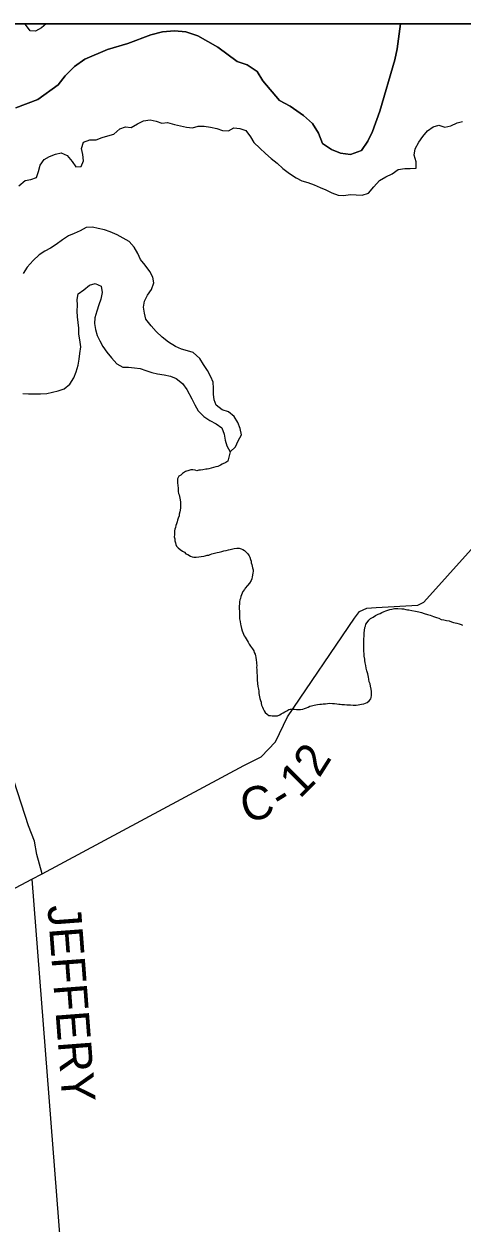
# Model space of a CAD drawing. Extents: x 0.4 to 34.4, y -2.1 to 19.9.
# Drawn here: x 6.349 to 7.097, y 16.79 to 18.836 of the extents above; entities that cross this region are included whole.
import ezdxf

# ---------------------------------------------------------------- set-up
doc = ezdxf.new("R2010")
doc.units = 0
for name, color, linetype in [('GM_X_County', 7, 'Continuous'), ('GM_X_County_Road', 7, 'Continuous'), ('GM_X_County_Road_Text', 7, 'Continuous'), ('GM_X_Major_Lake', 7, 'Continuous'), ('GM_X_Minor_River', 7, 'Continuous'), ('GM_X_Township', 7, 'Continuous'), ('SH_Data', 7, 'Continuous')]:
    doc.layers.add(name, color=color, linetype=linetype)

msp = doc.modelspace()

# ---------------------------------------------------------------- linework, layer by layer
at = {"layer": 'GM_X_County'}
msp.add_lwpolyline([(9.8001, 15.3423), (9.8001, 18.8357), (3.0001, 18.8357), (3.0001, 12.0357), (9.5074, 12.0357)], dxfattribs=at)
at = {"layer": 'GM_X_County_Road'}
for points in [[(5.0993, 16.7069), (5.2822, 16.8039), (5.7558, 17.055), (6.3625, 17.3767), (6.38, 17.386), (6.7247, 17.5708), (6.7542, 17.5855), (6.7786, 17.6112), (6.7991, 17.6537), (6.9135, 17.8219), (6.9221, 17.8335), (6.9343, 17.8393), (6.9503, 17.8402), (7.0217, 17.8445), (7.032, 17.8492), (7.2391, 18.0795)], [(6.38, 17.386), (6.3711, 17.4191), (6.3668, 17.4419), (6.3569, 17.4679), (6.3072, 17.6191), (6.2919, 17.6694), (6.2797, 17.6961), (6.2758, 17.722), (6.2794, 17.7477), (6.2904, 17.8277), (6.2982, 17.9054), (6.2953, 17.9525), (6.2908, 17.9658), (6.2906, 17.9665)], [(6.3625, 17.3767), (6.4528, 16.2176), (6.4539, 16.203)]]:
    msp.add_lwpolyline(points, dxfattribs=at)
at = {"layer": 'GM_X_Major_Lake'}
for points in [[(6.3867, 18.8357), (6.3789, 18.8292), (6.3689, 18.8233), (6.3595, 18.8242), (6.3516, 18.8346), (6.3515, 18.8357)], [(6.3402, 18.5598), (6.3509, 18.5684), (6.3608, 18.5701), (6.3704, 18.5738), (6.3739, 18.5843), (6.3768, 18.5949), (6.3834, 18.6047), (6.3929, 18.6094), (6.4029, 18.6135), (6.4128, 18.616), (6.4229, 18.6113), (6.4311, 18.6013), (6.4374, 18.5917), (6.4469, 18.5923), (6.4505, 18.6025), (6.4495, 18.6131), (6.4474, 18.6234), (6.4506, 18.634), (6.4617, 18.6383), (6.4723, 18.6382), (6.4826, 18.6422), (6.4922, 18.6451), (6.5025, 18.6476), (6.5125, 18.6569)], [(6.5125, 18.6569), (6.5224, 18.6601), (6.5322, 18.6592), (6.543, 18.6651), (6.5533, 18.6703), (6.5643, 18.672), (6.5745, 18.6699), (6.5847, 18.6664), (6.5942, 18.6674), (6.6063, 18.6641), (6.6162, 18.6617), (6.6264, 18.6597), (6.6366, 18.6587), (6.6465, 18.6612), (6.6568, 18.6611), (6.6674, 18.6598), (6.6783, 18.6573), (6.6882, 18.6542), (6.698, 18.6532), (6.7076, 18.6584), (6.7178, 18.6575), (6.728, 18.6539), (6.7358, 18.6432), (6.7414, 18.6336), (6.7515, 18.6236), (6.7616, 18.6147), (6.7713, 18.6062), (6.7811, 18.5981), (6.7908, 18.5892), (6.8024, 18.5807), (6.8137, 18.5733), (6.8235, 18.5682), (6.8337, 18.565), (6.8446, 18.5615), (6.8548, 18.5568), (6.8646, 18.5528), (6.8744, 18.5477), (6.8857, 18.5438), (6.8952, 18.5429), (6.9059, 18.5446), (6.9165, 18.5444), (6.9267, 18.5439), (6.9374, 18.5471), (6.9463, 18.558), (6.956, 18.5688), (6.9671, 18.5751), (6.9778, 18.5799), (6.9881, 18.5877), (6.9992, 18.589), (7.0086, 18.5889), (7.0185, 18.5895), (7.0187, 18.6005), (7.0155, 18.6119), (7.0171, 18.6229), (7.023, 18.6338), (7.03, 18.6439), (7.0381, 18.6536), (7.0477, 18.6603), (7.0576, 18.6628), (7.0678, 18.6596), (7.0777, 18.6621), (7.0884, 18.6669), (7.098, 18.6694)], [(6.7142, 18.1559), (6.7079, 18.1662), (6.6982, 18.1739), (6.6872, 18.1775), (6.6771, 18.1853), (6.6738, 18.1948), (6.6724, 18.2043), (6.6726, 18.2142), (6.672, 18.2244), (6.6683, 18.2339), (6.6624, 18.2446), (6.6558, 18.255), (6.6491, 18.2653), (6.6382, 18.275), (6.628, 18.2782), (6.6182, 18.281), (6.6077, 18.2857), (6.5956, 18.2931), (6.5851, 18.3016), (6.575, 18.3112), (6.5665, 18.3208), (6.5571, 18.332), (6.555, 18.3423), (6.5533, 18.3525), (6.555, 18.3627), (6.5597, 18.3729), (6.5667, 18.383), (6.5706, 18.3943), (6.5693, 18.4038), (6.5641, 18.4134), (6.5559, 18.4241), (6.5481, 18.4341), (6.5437, 18.4441), (6.537, 18.4548), (6.5285, 18.4644), (6.5187, 18.4702), (6.5081, 18.4757), (6.4964, 18.4812), (6.4863, 18.4844), (6.476, 18.4868), (6.4658, 18.4889), (6.4552, 18.4883), (6.4452, 18.4827), (6.4345, 18.4784), (6.425, 18.474), (6.4146, 18.4673), (6.4039, 18.4595), (6.3943, 18.4532), (6.3847, 18.448), (6.3748, 18.4421), (6.3647, 18.4324), (6.3543, 18.4208), (6.3477, 18.4103)], [(6.3472, 18.2056), (6.3566, 18.2047), (6.3669, 18.2049), (6.3775, 18.2047), (6.3882, 18.2053), (6.3977, 18.2078), (6.4076, 18.2099), (6.4175, 18.2132), (6.4275, 18.2214), (6.4341, 18.2319), (6.4381, 18.2424), (6.4417, 18.2534), (6.4433, 18.264), (6.4446, 18.2738), (6.4459, 18.2848), (6.4446, 18.2966), (6.4429, 18.3068), (6.4426, 18.3167), (6.4417, 18.3262), (6.4403, 18.3361), (6.4401, 18.3456), (6.4406, 18.3562), (6.44, 18.3657), (6.4417, 18.3755), (6.4513, 18.3822), (6.4609, 18.3904), (6.4708, 18.3932), (6.4806, 18.3882), (6.4823, 18.3775), (6.4802, 18.3665), (6.4767, 18.3567), (6.4735, 18.3458), (6.4703, 18.3345), (6.4697, 18.3246), (6.4711, 18.3147), (6.4743, 18.3044), (6.4787, 18.2949), (6.4835, 18.2853), (6.4906, 18.2758), (6.4984, 18.2662), (6.5074, 18.2562), (6.5179, 18.2503), (6.5278, 18.2505), (6.5376, 18.2492), (6.5475, 18.2479), (6.5573, 18.2444), (6.5671, 18.2412), (6.5773, 18.2388), (6.5887, 18.2374), (6.5993, 18.235), (6.6091, 18.2311), (6.6196, 18.2226), (6.6274, 18.2122), (6.6355, 18.1965), (6.6406, 18.1858), (6.6466, 18.1755), (6.6559, 18.1659), (6.6664, 18.1593), (6.677, 18.1538), (6.6867, 18.1468), (6.6907, 18.1361), (6.6925, 18.1255), (6.6954, 18.116), (6.7009, 18.106), (6.7105, 18.1142), (6.7145, 18.1244), (6.7203, 18.1349), (6.7182, 18.1456), (6.7142, 18.1559)]]:
    msp.add_lwpolyline(points, dxfattribs=at)
at = {"layer": 'GM_X_Minor_River'}
for points in [[(6.7009, 18.106), (6.6971, 18.0898), (6.6936, 18.0879), (6.6874, 18.0846), (6.6847, 18.0831), (6.6801, 18.0809), (6.6766, 18.0802), (6.6728, 18.0792), (6.6686, 18.0781), (6.6648, 18.077), (6.6621, 18.0763), (6.6594, 18.076), (6.6544, 18.0749), (6.6506, 18.0746), (6.6475, 18.0743), (6.6441, 18.0736), (6.6414, 18.0744), (6.6376, 18.0749), (6.6342, 18.0749), (6.6308, 18.0742), (6.625, 18.072), (6.6196, 18.0691), (6.6169, 18.0661), (6.6134, 18.0643), (6.6114, 18.0597), (6.6113, 18.0559), (6.6112, 18.0525), (6.6115, 18.0487), (6.6121, 18.043), (6.6124, 18.0384), (6.6131, 18.035), (6.6138, 18.0323), (6.6145, 18.0296), (6.6152, 18.027), (6.6155, 18.0239), (6.6162, 18.0197), (6.6161, 18.0167), (6.6164, 18.0132), (6.6164, 18.0102), (6.6159, 18.0064), (6.6151, 18.0034), (6.6138, 17.9996), (6.6138, 17.9969), (6.6121, 17.9928), (6.6113, 17.9894), (6.6105, 17.9863), (6.6096, 17.9829), (6.6084, 17.9799), (6.6076, 17.9769), (6.6068, 17.9739), (6.6063, 17.9712), (6.6058, 17.9666), (6.6058, 17.964), (6.6057, 17.9609), (6.6064, 17.9575), (6.6067, 17.9541), (6.6078, 17.9503), (6.6085, 17.9476), (6.6095, 17.9449), (6.6122, 17.9422), (6.6155, 17.9391), (6.62, 17.9363), (6.623, 17.9344), (6.6256, 17.9321), (6.6287, 17.9305), (6.6336, 17.9281), (6.6362, 17.9269), (6.6392, 17.9261), (6.643, 17.926), (6.6476, 17.9267), (6.6515, 17.9274), (6.6561, 17.9281), (6.6587, 17.9284), (6.6618, 17.9295), (6.6645, 17.9298), (6.6672, 17.9305), (6.6699, 17.9316), (6.6745, 17.9327), (6.6787, 17.9341), (6.6825, 17.9348), (6.6867, 17.9359), (6.6902, 17.937), (6.694, 17.9376), (6.6982, 17.9387), (6.7009, 17.9394), (6.7055, 17.9405), (6.7082, 17.9408), (6.7124, 17.9415), (6.7162, 17.9414), (6.72, 17.9402), (6.7227, 17.9394), (6.7257, 17.9374)], [(6.7257, 17.9374), (6.729, 17.9343), (6.7312, 17.9316), (6.7335, 17.9286), (6.7346, 17.9259), (6.7356, 17.9224), (6.7367, 17.9194), (6.737, 17.9167), (6.7381, 17.9136), (6.7388, 17.9106), (6.7395, 17.9079), (6.7402, 17.9045), (6.7401, 17.9018), (6.7397, 17.8992), (6.7392, 17.8954), (6.7388, 17.8927), (6.7379, 17.8893), (6.7367, 17.8863), (6.7343, 17.8818), (6.7308, 17.8776), (6.7269, 17.8735), (6.7253, 17.8709), (6.7229, 17.8675), (6.7217, 17.8649), (6.7205, 17.8618), (6.7193, 17.8588), (6.7185, 17.8558), (6.7177, 17.8531), (6.7172, 17.8497), (6.7168, 17.8471), (6.7166, 17.8421), (6.7166, 17.8379), (6.7168, 17.8338), (6.7171, 17.8284), (6.717, 17.8242), (6.7173, 17.8212), (6.718, 17.8162), (6.7186, 17.812), (6.7193, 17.8094), (6.7204, 17.8044), (6.7214, 17.8006), (6.7229, 17.7975), (6.7236, 17.7948), (6.7251, 17.7921), (6.7265, 17.7895), (6.7284, 17.7868), (6.7302, 17.7837), (6.7317, 17.781), (6.7335, 17.7779), (6.7361, 17.7744), (6.7394, 17.7698), (6.7416, 17.7664), (6.7423, 17.7637), (6.7438, 17.7606), (6.7445, 17.7579), (6.7452, 17.7553), (6.7455, 17.7503), (6.7458, 17.7473), (6.7461, 17.7446), (6.7464, 17.7412), (6.7463, 17.7381), (6.7466, 17.7343), (6.7469, 17.729), (6.7472, 17.724), (6.7474, 17.7202), (6.7474, 17.7168), (6.748, 17.7107), (6.7486, 17.7057), (6.7493, 17.7008), (6.75, 17.6973), (6.7503, 17.6935), (6.7513, 17.6878), (6.752, 17.6851), (6.7531, 17.6817), (6.7538, 17.679), (6.7541, 17.6764), (6.7548, 17.6737), (6.7562, 17.6702), (6.7573, 17.6672), (6.7591, 17.6641), (6.761, 17.6614), (6.764, 17.6583), (6.7674, 17.6563), (6.77, 17.6559), (6.7727, 17.6555), (6.7753, 17.6554), (6.7792, 17.6554), (6.7822, 17.6557), (6.7857, 17.6571), (6.7884, 17.6586), (6.7915, 17.6605), (6.7946, 17.6623), (6.798, 17.6641), (6.8011, 17.666), (6.8038, 17.6667), (6.8073, 17.667), (6.8107, 17.6669), (6.8141, 17.6661), (6.8175, 17.6661), (6.821, 17.666), (6.8252, 17.6671)], [(6.8252, 17.6671), (6.8279, 17.6678), (6.8313, 17.6692), (6.834, 17.6703), (6.8371, 17.6718), (6.8402, 17.6725), (6.8444, 17.6739), (6.8471, 17.6743), (6.8501, 17.6746), (6.8543, 17.6753), (6.857, 17.6756), (6.8601, 17.6759), (6.8639, 17.6762), (6.8673, 17.6766), (6.8715, 17.6769), (6.8761, 17.6764), (6.8795, 17.6763), (6.8833, 17.6759), (6.8864, 17.6755), (6.889, 17.6754), (6.8917, 17.675), (6.8963, 17.6749), (6.9004, 17.6744), (6.9031, 17.6744), (6.9065, 17.6743), (6.9111, 17.6739), (6.9138, 17.6738), (6.9164, 17.6738), (6.9195, 17.6741), (6.9226, 17.6748), (6.9256, 17.6755), (6.9291, 17.6762), (6.9321, 17.6769), (6.9348, 17.6784), (6.9383, 17.681), (6.9411, 17.6843), (6.9419, 17.687), (6.9424, 17.6904), (6.9424, 17.6931), (6.9425, 17.6969), (6.9418, 17.7007), (6.9408, 17.706), (6.9401, 17.7098), (6.9387, 17.7137), (6.938, 17.7179), (6.9373, 17.7213), (6.9359, 17.727), (6.9345, 17.7324), (6.9335, 17.737), (6.9328, 17.7412), (6.9318, 17.7458), (6.9311, 17.7496), (6.9312, 17.7522), (6.9301, 17.7572), (6.9298, 17.761), (6.9296, 17.7656), (6.9293, 17.7694), (6.9294, 17.7728), (6.9295, 17.7774), (6.9292, 17.7827), (6.9293, 17.7865), (6.9298, 17.7922), (6.9299, 17.7971), (6.9304, 17.8009), (6.9312, 17.8059), (6.9321, 17.8085), (6.9329, 17.8119), (6.9349, 17.8146), (6.938, 17.8187), (6.9407, 17.8213), (6.945, 17.8239), (6.9492, 17.8265), (6.9539, 17.829), (6.9573, 17.8301), (6.96, 17.8316), (6.9639, 17.8334), (6.967, 17.8345), (6.9704, 17.836), (6.9735, 17.8371), (6.9773, 17.8377), (6.9815, 17.8388), (6.9842, 17.8388), (6.9876, 17.8387), (6.9941, 17.8382), (6.9972, 17.8378), (7.0009, 17.8369), (7.0036, 17.8365), (7.0063, 17.8361), (7.0112, 17.8352), (7.0173, 17.834), (7.023, 17.8327), (7.0275, 17.8319), (7.0324, 17.8303), (7.0381, 17.8283), (7.0423, 17.8274), (7.048, 17.825), (7.0533, 17.823), (7.0574, 17.8218), (7.0616, 17.8198), (7.0657, 17.819), (7.0703, 17.8182)], [(7.0703, 17.8182), (7.0749, 17.8173), (7.079, 17.8157), (7.0824, 17.8149), (7.0881, 17.8133), (7.0923, 17.8124), (7.0953, 17.8112), (7.098, 17.8104)]]:
    msp.add_lwpolyline(points, dxfattribs=at)
at = {"layer": 'GM_X_Township'}
for points in [[(6.992, 18.8357), (3.0001, 18.8357), (3.0001, 17.934)], [(6.992, 18.8357), (6.9861, 18.7933), (6.982, 18.7744), (6.9568, 18.6869), (6.9439, 18.6523), (6.936, 18.6358), (6.9251, 18.6197), (6.9067, 18.6128), (6.8897, 18.6154), (6.8743, 18.6218), (6.8589, 18.6316), (6.852, 18.6495), (6.8417, 18.666), (6.8264, 18.6796), (6.8036, 18.6956), (6.7855, 18.7054), (6.7569, 18.7386), (6.7474, 18.7547), (6.7301, 18.7657), (6.7128, 18.7717), (6.6802, 18.7959), (6.6457, 18.8155), (6.6257, 18.8223), (6.606, 18.8242), (6.5858, 18.822), (6.5656, 18.817), (6.5266, 18.8023), (6.4915, 18.7923), (6.4528, 18.7756), (6.4351, 18.7631), (6.4196, 18.7471), (6.4076, 18.7318), (6.3726, 18.7066), (6.3351, 18.6926)], [(6.3351, 18.6926), (6.3726, 18.7066), (6.4076, 18.7318), (6.4196, 18.7471), (6.4351, 18.7631), (6.4528, 18.7756), (6.4915, 18.7923), (6.5266, 18.8023), (6.5656, 18.817), (6.5858, 18.822), (6.606, 18.8242), (6.6257, 18.8223), (6.6457, 18.8155), (6.6802, 18.7959), (6.7128, 18.7717), (6.7301, 18.7657), (6.7474, 18.7547), (6.7569, 18.7386), (6.7855, 18.7054), (6.8036, 18.6956), (6.8264, 18.6796), (6.8417, 18.666), (6.852, 18.6495), (6.8589, 18.6316), (6.8743, 18.6218), (6.8897, 18.6154), (6.9067, 18.6128), (6.9251, 18.6197), (6.936, 18.6358), (6.9439, 18.6523), (6.9568, 18.6869), (6.982, 18.7744), (6.9861, 18.7933), (6.992, 18.8357)], [(9.8001, 15.535), (9.8001, 18.8357), (6.992, 18.8357)]]:
    msp.add_lwpolyline(points, dxfattribs=at)
at = {"layer": 'SH_Data'}
msp.add_line((3.0001, 18.8357), (9.8001, 18.8357), dxfattribs=at)

# ---------------------------------------------------------------- texts
at = {"layer": 'GM_X_County_Road_Text'}
for s, height, rotation, p in [('2', 0.0568, 57.6289, (6.8532, 17.5482)), ('1', 0.0568, 45.2544, (6.8202, 17.5129)), ('C', 0.0568, 15.1836, (6.7275, 17.4723)), ('-', 0.0568, 31.4922, (6.7887, 17.4915)), ('JEFFERY', 0.05682, 274.3476, (6.3892, 17.3313))]:
    msp.add_text(s, height=height, rotation=rotation, dxfattribs=at).set_placement(p)

doc.saveas('drawing.dxf')
